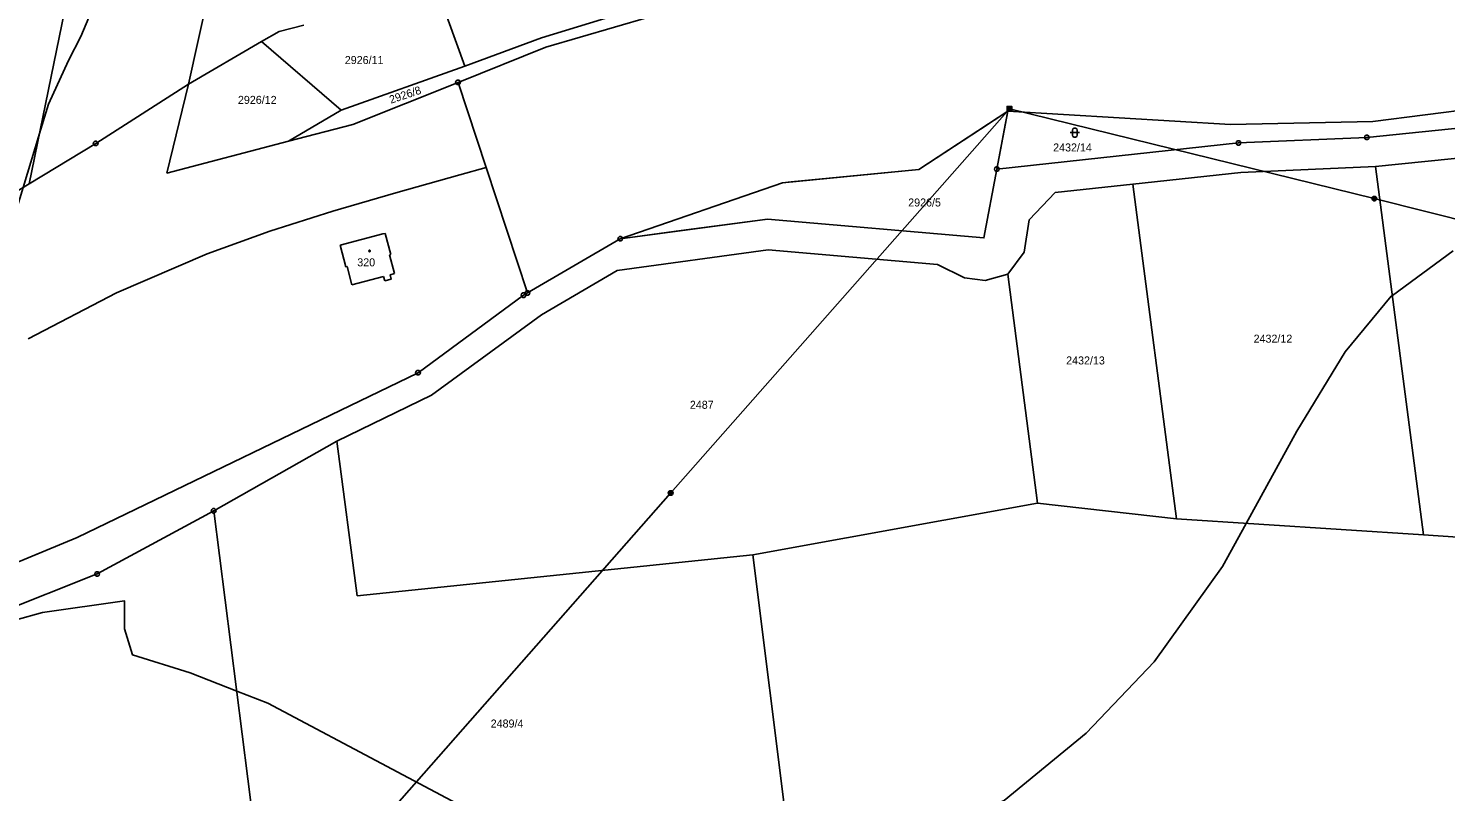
# Model space of a CAD drawing. Extents: x -760611 to -758411, y -1176479 to -1174807.
# Drawn here: x -759278.5 to -758977.4, y -1175293 to -1175131 of the extents above; entities that cross this region are included whole.
import ezdxf

# ---------------------------------------------------------------- set-up
doc = ezdxf.new("R2010")
doc.units = 0
for name, color, linetype in [('1', 7, 'Continuous'), ('11', 7, 'Continuous'), ('12', 7, 'Continuous'), ('2', 7, 'Continuous'), ('3', 7, 'Continuous'), ('5', 7, 'Continuous'), ('6', 7, 'Continuous'), ('8', 7, 'Continuous')]:
    doc.layers.add(name, color=color, linetype=linetype)

msp = doc.modelspace()

# ---------------------------------------------------------------- linework, layer by layer
at = {"layer": '1'}
for p, q in [((-759231.31, -1175082.74), (-759244.42, -1175142.81)), ((-759278.28, -1175163.97), (-759268.08, -1175114.33)), ((-759191.41, -1175123.23), (-759185.78, -1175139)), ((-759149.08, -1175126.73), (-759169.45, -1175133.02)), ((-759168.57, -1175134.99), (-759146.64, -1175128.58)), ((-759225.2, -1175131.63), (-759228.94, -1175133.8)), ((-759219.93, -1175130.32), (-759225.2, -1175131.63)), ((-759228.94, -1175133.8), (-759244.42, -1175142.81)), ((-759228.94, -1175133.8), (-759212.03, -1175148.33)), ((-759169.45, -1175133.02), (-759185.78, -1175139)), ((-759187.2, -1175142.44), (-759168.57, -1175134.99)), ((-759185.78, -1175139), (-759212.03, -1175148.33)), ((-759264.16, -1175155.41), (-759244.42, -1175142.81)), ((-759244.42, -1175142.81), (-759249.02, -1175161.71)), ((-759209.52, -1175151.37), (-759187.2, -1175142.44)), ((-759187.2, -1175142.44), (-759181.22, -1175160.55)), ((-759212.03, -1175148.33), (-759223.2, -1175154.95)), ((-759070.44, -1175148.56), (-759089.31, -1175160.91)), ((-759070.44, -1175148.56), (-759072.75, -1175160.86)), ((-759023.11, -1175151.42), (-759070.44, -1175148.56)), ((-758969.53, -1175147.78), (-758992.89, -1175150.76)), ((-759223.2, -1175154.95), (-759209.52, -1175151.37)), ((-758992.89, -1175150.76), (-759023.11, -1175151.42)), ((-758994.13, -1175154.13), (-758963.42, -1175151.02)), ((-759278.28, -1175163.97), (-759264.16, -1175155.41)), ((-759249.02, -1175161.71), (-759223.2, -1175154.95)), ((-759072.75, -1175160.86), (-759021.39, -1175155.3)), ((-759021.39, -1175155.3), (-758994.13, -1175154.13)), ((-758968.01, -1175157.83), (-758992.28, -1175160.27)), ((-759181.22, -1175160.55), (-759172.44, -1175187.15)), ((-759089.31, -1175160.91), (-759118.24, -1175163.75)), ((-759075.49, -1175175.45), (-759072.75, -1175160.86)), ((-759020.91, -1175161.58), (-759043.83, -1175164.05)), ((-758992.28, -1175160.27), (-759020.91, -1175161.58)), ((-758982.14, -1175238.54), (-758992.28, -1175160.27)), ((-759306.6, -1175181.08), (-759278.28, -1175163.97)), ((-759118.24, -1175163.75), (-759152.73, -1175175.66)), ((-759043.83, -1175164.05), (-759060.33, -1175165.82)), ((-759034.58, -1175235.13), (-759043.83, -1175164.05)), ((-759060.33, -1175165.82), (-759065.91, -1175171.64)), ((-759121.49, -1175171.46), (-759152.73, -1175175.66)), ((-759075.49, -1175175.45), (-759121.49, -1175171.46)), ((-759065.91, -1175171.64), (-759066.96, -1175178.52)), ((-759212.21, -1175176.99), (-759203.17, -1175174.63)), ((-759211.01, -1175181.6), (-759212.21, -1175176.99)), ((-759203.17, -1175174.63), (-759202.69, -1175174.5)), ((-759202.69, -1175174.5), (-759201.49, -1175179)), ((-759152.73, -1175175.66), (-759172.44, -1175187.15)), ((-759201.49, -1175179), (-759201.73, -1175179.07)), ((-759201.73, -1175179.07), (-759200.68, -1175183.03)), ((-759121.33, -1175178), (-759153.39, -1175182.41)), ((-759085.37, -1175181.12), (-759121.33, -1175178)), ((-759066.96, -1175178.52), (-759070.42, -1175183.14)), ((-759210.77, -1175181.53), (-759211.01, -1175181.6)), ((-759209.76, -1175185.41), (-759210.77, -1175181.53)), ((-759200.68, -1175183.03), (-759201.61, -1175183.27)), ((-759153.39, -1175182.41), (-759169.44, -1175191.77)), ((-759079.59, -1175183.96), (-759085.37, -1175181.12)), ((-759070.42, -1175183.14), (-759075.22, -1175184.54)), ((-759070.42, -1175183.14), (-759064.12, -1175231.78)), ((-759203.01, -1175183.64), (-759209.76, -1175185.41)), ((-759202.77, -1175184.56), (-759203.01, -1175183.64)), ((-759201.37, -1175184.19), (-759202.77, -1175184.56)), ((-759201.61, -1175183.27), (-759201.37, -1175184.19)), ((-759075.22, -1175184.54), (-759079.59, -1175183.96)), ((-759173.27, -1175187.63), (-759195.69, -1175204.09)), ((-759172.44, -1175187.15), (-759173.27, -1175187.63)), ((-759169.44, -1175191.77), (-759192.85, -1175208.83)), ((-759195.69, -1175204.09), (-759268.1, -1175239.07)), ((-759192.85, -1175208.83), (-759212.91, -1175218.59)), ((-759239.1, -1175233.43), (-759212.91, -1175218.59)), ((-759212.91, -1175218.59), (-759208.65, -1175251.43)), ((-759239.1, -1175233.43), (-759263.85, -1175246.81)), ((-759239.1, -1175233.43), (-759230.51, -1175300.62)), ((-759064.12, -1175231.78), (-759124.57, -1175242.76)), ((-759034.58, -1175235.13), (-759064.12, -1175231.78)), ((-759034.58, -1175235.13), (-758982.14, -1175238.54)), ((-759268.1, -1175239.07), (-759307.24, -1175255.34)), ((-758880.06, -1175245.42), (-758982.14, -1175238.54)), ((-759208.65, -1175251.43), (-759124.57, -1175242.76)), ((-759124.57, -1175242.76), (-759116.61, -1175306.03)), ((-759263.85, -1175246.81), (-759298.74, -1175260.61))]:
    msp.add_line(p, q, dxfattribs=at)
at = {"layer": '11'}
for points in [[(-759302.17, -1175262.03), (-759302.03, -1175261.55), (-759299.47, -1175252.11), (-759298.73, -1175249.35), (-759297.4, -1175234.13), (-759293.92, -1175210.45), (-759292.63, -1175205.38), (-759291.77, -1175202), (-759288.78, -1175195.24), (-759288.34, -1175191.86), (-759285.77, -1175185.1), (-759279.57, -1175164.75), (-759276.09, -1175153.33), (-759274.19, -1175147.08), (-759269.92, -1175137.79), (-759267.35, -1175132.72), (-759260.94, -1175117.52), (-759255.81, -1175107.39), (-759254.95, -1175102.32), (-759253.24, -1175098.94), (-759251.12, -1175100.22), (-759246.85, -1175092.2)], [(-759118.24, -1175163.75), (-759116.45, -1175163.57), (-759089.31, -1175160.91), (-759076.24, -1175152.36), (-759070.44, -1175148.56), (-759070.91, -1175151.09), (-759072.75, -1175160.86)], [(-759072.75, -1175160.86), (-759075.49, -1175175.45), (-759121.49, -1175171.46), (-759139.78, -1175173.92), (-759152.73, -1175175.66), (-759118.24, -1175163.75)], [(-758975.79, -1175178.19), (-758988.73, -1175187.68), (-758988.97, -1175187.85), (-758998.77, -1175199.65), (-759009, -1175216.53), (-759019.77, -1175236.09), (-759024.8, -1175245.22), (-759039.29, -1175265.46), (-759053.76, -1175280.62), (-759071.19, -1175294.92), (-759092, -1175303.7), (-759103.96, -1175308.13), (-759129.09, -1175317.42), (-759132.3, -1175318.61)], [(-759132.3, -1175318.61), (-759156.06, -1175311), (-759167.91, -1175305.86), (-759171.08, -1175304.18), (-759174.75, -1175302.24), (-759227.58, -1175274.25), (-759234.21, -1175271.67), (-759244.09, -1175267.82), (-759256.38, -1175263.95), (-759258.05, -1175258.44), (-759258.03, -1175252.52), (-759275.43, -1175254.97), (-759297.92, -1175261.21), (-759298.65, -1175261.35), (-759302.17, -1175262.03)]]:
    msp.add_lwpolyline(points, dxfattribs=at)
at = {"layer": '12'}
for p, q in [((-759212.21, -1175176.99), (-759203.17, -1175174.63)), ((-759211.01, -1175181.6), (-759212.21, -1175176.99)), ((-759203.17, -1175174.63), (-759202.69, -1175174.5)), ((-759202.69, -1175174.5), (-759201.49, -1175179)), ((-759201.49, -1175179), (-759201.73, -1175179.07)), ((-759201.73, -1175179.07), (-759200.68, -1175183.03)), ((-759210.77, -1175181.53), (-759211.01, -1175181.6)), ((-759209.76, -1175185.41), (-759210.77, -1175181.53)), ((-759200.68, -1175183.03), (-759201.61, -1175183.27)), ((-759203.01, -1175183.64), (-759209.76, -1175185.41)), ((-759202.77, -1175184.56), (-759203.01, -1175183.64)), ((-759201.37, -1175184.19), (-759202.77, -1175184.56)), ((-759201.61, -1175183.27), (-759201.37, -1175184.19))]:
    msp.add_line(p, q, dxfattribs=at)
at = {"layer": '3'}
msp.add_lwpolyline([(-759056.68, -1175152.62), (-759056.58, -1175152.33), (-759056.33, -1175152.15), (-759056.02, -1175152.15), (-759055.77, -1175152.33), (-759055.67, -1175152.62), (-759055.67, -1175153.62), (-759055.77, -1175153.91), (-759056.02, -1175154.09), (-759056.33, -1175154.09), (-759056.58, -1175153.91), (-759056.68, -1175153.62)], close=True, dxfattribs=at)
msp.add_lwpolyline([(-759057.18, -1175153.12), (-759055.91, -1175153.12), (-759055.18, -1175153.12)], dxfattribs=at)
at = {"layer": '5'}
msp.add_lwpolyline([(-759206.01, -1175178.06), (-759205.91, -1175178.08), (-759205.86, -1175178.17), (-759205.84, -1175178.23), (-759205.86, -1175178.32), (-759205.94, -1175178.39), (-759206.01, -1175178.4), (-759206.1, -1175178.37), (-759206.16, -1175178.31), (-759206.18, -1175178.23), (-759206.16, -1175178.14), (-759206.08, -1175178.07)], close=True, dxfattribs=at)
at = {"layer": '6'}
for p, q in [((-759070.08, -1175148.04), (-759142.03, -1175229.64)), ((-758992.56, -1175167.12), (-759070.08, -1175148.04)), ((-759181.22, -1175160.55), (-759186.83, -1175162.1)), ((-759186.83, -1175162.1), (-759200.44, -1175165.88)), ((-759200.44, -1175165.88), (-759213.77, -1175169.78)), ((-758915.88, -1175186.35), (-758992.56, -1175167.12)), ((-759213.77, -1175169.78), (-759227.17, -1175174.06)), ((-759227.17, -1175174.06), (-759240.47, -1175178.85)), ((-759240.47, -1175178.85), (-759259.71, -1175187.11)), ((-759259.71, -1175187.11), (-759278.52, -1175196.88)), ((-759142.03, -1175229.64), (-759220.08, -1175318.2))]:
    msp.add_line(p, q, dxfattribs=at)
for points in [[(-759070.58, -1175147.54), (-759069.58, -1175147.54), (-759069.58, -1175148.54), (-759070.58, -1175148.54), (-759070.58, -1175147.54), (-759070.52, -1175147.6), (-759069.64, -1175147.6), (-759069.64, -1175147.68), (-759070.52, -1175147.68), (-759070.52, -1175147.76), (-759069.64, -1175147.76), (-759069.64, -1175147.84), (-759070.52, -1175147.84), (-759070.52, -1175147.92), (-759069.64, -1175147.92), (-759069.64, -1175148), (-759070.52, -1175148), (-759070.52, -1175148.08), (-759069.64, -1175148.08), (-759069.64, -1175148.16), (-759070.52, -1175148.16), (-759070.52, -1175148.24), (-759069.64, -1175148.24), (-759069.64, -1175148.32), (-759070.52, -1175148.32), (-759070.52, -1175148.4), (-759069.64, -1175148.4), (-759069.64, -1175148.48), (-759070.52, -1175148.48)], [(-758992.71, -1175166.64), (-758992.4, -1175166.64), (-758992.15, -1175166.82), (-758992.05, -1175167.11), (-758992.15, -1175167.4), (-758992.4, -1175167.58), (-758992.71, -1175167.58), (-758992.96, -1175167.4), (-758993.06, -1175167.11), (-758992.96, -1175166.82), (-758992.71, -1175166.64), (-758992.68, -1175166.68), (-758992.44, -1175166.68), (-758992.28, -1175166.76), (-758992.84, -1175166.76), (-758992.92, -1175166.84), (-758992.2, -1175166.84), (-758992.2, -1175166.92), (-758992.92, -1175166.92), (-758992.96, -1175167), (-758992.16, -1175167), (-758992.12, -1175167.08), (-758993, -1175167.08), (-758993, -1175167.16), (-758992.12, -1175167.16), (-758992.15, -1175167.24), (-758992.96, -1175167.24), (-758992.95, -1175167.32), (-758992.14, -1175167.32), (-758992.19, -1175167.4), (-758992.91, -1175167.4), (-758992.83, -1175167.48), (-758992.27, -1175167.48), (-758992.38, -1175167.56), (-758992.72, -1175167.56)], [(-759142.18, -1175229.16), (-759141.87, -1175229.16), (-759141.62, -1175229.34), (-759141.52, -1175229.63), (-759141.62, -1175229.92), (-759141.87, -1175230.1), (-759142.18, -1175230.1), (-759142.43, -1175229.92), (-759142.53, -1175229.63), (-759142.43, -1175229.34), (-759142.18, -1175229.16), (-759142.15, -1175229.2), (-759141.91, -1175229.2), (-759141.75, -1175229.28), (-759142.31, -1175229.28), (-759142.39, -1175229.36), (-759141.67, -1175229.36), (-759141.67, -1175229.44), (-759142.39, -1175229.44), (-759142.43, -1175229.52), (-759141.63, -1175229.52), (-759141.59, -1175229.6), (-759142.47, -1175229.6), (-759142.47, -1175229.68), (-759141.59, -1175229.68), (-759141.62, -1175229.76), (-759142.43, -1175229.76), (-759142.42, -1175229.84), (-759141.61, -1175229.84), (-759141.66, -1175229.92), (-759142.38, -1175229.92), (-759142.3, -1175230), (-759141.74, -1175230), (-759141.85, -1175230.08), (-759142.19, -1175230.08)]]:
    msp.add_lwpolyline(points, dxfattribs=at)
at = {"layer": '8'}
for p, q in [((-759187.32, -1175142.44), (-759187.08, -1175142.44)), ((-759264.28, -1175155.41), (-759264.04, -1175155.41)), ((-759021.51, -1175155.3), (-759021.27, -1175155.3)), ((-758994.25, -1175154.13), (-758994.01, -1175154.13)), ((-759072.87, -1175160.86), (-759072.63, -1175160.86)), ((-759152.85, -1175175.66), (-759152.61, -1175175.66)), ((-759173.39, -1175187.63), (-759173.15, -1175187.63)), ((-759172.56, -1175187.15), (-759172.32, -1175187.15)), ((-759195.81, -1175204.09), (-759195.57, -1175204.09)), ((-759239.22, -1175233.43), (-759238.98, -1175233.43)), ((-759263.97, -1175246.81), (-759263.73, -1175246.81))]:
    msp.add_line(p, q, dxfattribs=at)
for points in [[(-759187.05, -1175141.96), (-759186.8, -1175142.14), (-759186.7, -1175142.43), (-759186.8, -1175142.72), (-759187.05, -1175142.9), (-759187.36, -1175142.9), (-759187.61, -1175142.72), (-759187.71, -1175142.43), (-759187.61, -1175142.14), (-759187.36, -1175141.96)], [(-759264.01, -1175154.93), (-759263.76, -1175155.11), (-759263.66, -1175155.4), (-759263.76, -1175155.69), (-759264.01, -1175155.87), (-759264.32, -1175155.87), (-759264.57, -1175155.69), (-759264.67, -1175155.4), (-759264.57, -1175155.11), (-759264.32, -1175154.93)], [(-759021.24, -1175154.82), (-759020.99, -1175155), (-759020.89, -1175155.29), (-759020.99, -1175155.58), (-759021.24, -1175155.76), (-759021.55, -1175155.76), (-759021.8, -1175155.58), (-759021.9, -1175155.29), (-759021.8, -1175155), (-759021.55, -1175154.82)], [(-758993.98, -1175153.65), (-758993.73, -1175153.83), (-758993.63, -1175154.12), (-758993.73, -1175154.41), (-758993.98, -1175154.59), (-758994.29, -1175154.59), (-758994.54, -1175154.41), (-758994.64, -1175154.12), (-758994.54, -1175153.83), (-758994.29, -1175153.65)], [(-759072.6, -1175160.38), (-759072.35, -1175160.56), (-759072.25, -1175160.85), (-759072.35, -1175161.14), (-759072.6, -1175161.32), (-759072.91, -1175161.32), (-759073.16, -1175161.14), (-759073.26, -1175160.85), (-759073.16, -1175160.56), (-759072.91, -1175160.38)], [(-759152.58, -1175175.18), (-759152.33, -1175175.36), (-759152.23, -1175175.65), (-759152.33, -1175175.94), (-759152.58, -1175176.12), (-759152.89, -1175176.12), (-759153.14, -1175175.94), (-759153.24, -1175175.65), (-759153.14, -1175175.36), (-759152.89, -1175175.18)], [(-759173.12, -1175187.15), (-759172.87, -1175187.33), (-759172.77, -1175187.62), (-759172.87, -1175187.91), (-759173.12, -1175188.09), (-759173.43, -1175188.09), (-759173.68, -1175187.91), (-759173.78, -1175187.62), (-759173.68, -1175187.33), (-759173.43, -1175187.15)], [(-759172.29, -1175186.67), (-759172.04, -1175186.85), (-759171.94, -1175187.14), (-759172.04, -1175187.43), (-759172.29, -1175187.61), (-759172.6, -1175187.61), (-759172.85, -1175187.43), (-759172.95, -1175187.14), (-759172.85, -1175186.85), (-759172.6, -1175186.67)], [(-759195.54, -1175203.61), (-759195.29, -1175203.79), (-759195.19, -1175204.08), (-759195.29, -1175204.37), (-759195.54, -1175204.55), (-759195.85, -1175204.55), (-759196.1, -1175204.37), (-759196.2, -1175204.08), (-759196.1, -1175203.79), (-759195.85, -1175203.61)], [(-759238.95, -1175232.95), (-759238.7, -1175233.13), (-759238.6, -1175233.42), (-759238.7, -1175233.71), (-759238.95, -1175233.89), (-759239.26, -1175233.89), (-759239.51, -1175233.71), (-759239.61, -1175233.42), (-759239.51, -1175233.13), (-759239.26, -1175232.95)], [(-759263.7, -1175246.33), (-759263.45, -1175246.51), (-759263.35, -1175246.8), (-759263.45, -1175247.09), (-759263.7, -1175247.27), (-759264.01, -1175247.27), (-759264.26, -1175247.09), (-759264.36, -1175246.8), (-759264.26, -1175246.51), (-759264.01, -1175246.33)]]:
    msp.add_lwpolyline(points, close=True, dxfattribs=at)

# ---------------------------------------------------------------- texts
at = {"layer": '2'}
for s, p in [('2926/11', (-759211.25, -1175138.55)), ('2926/12', (-759233.95, -1175147.01)), ('2432/14', (-759060.78, -1175157.11)), ('2926/5', (-759091.57, -1175168.79)), ('320', (-759208.6, -1175181.5)), ('2432/12', (-759018.2, -1175197.71)), ('2432/13', (-759058.02, -1175202.33)), ('2487', (-759137.95, -1175211.75)), ('2489/4', (-759180.26, -1175279.42))]:
    msp.add_text(s, height=1.7, dxfattribs=at).set_placement(p)
msp.add_text('2926/8', height=1.7, rotation=18.4492, dxfattribs=at).set_placement((-759201.46, -1175146.99))

doc.saveas('drawing.dxf')
